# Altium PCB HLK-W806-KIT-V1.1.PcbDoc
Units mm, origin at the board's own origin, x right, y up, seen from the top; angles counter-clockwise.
Board outline 64 x 26 mm, 2 copper layers (Top Layer, Bottom Layer); 46 components, 64 nets, 229 pads, 212 vias.
Unrouted connection lines stored in the file: 24.
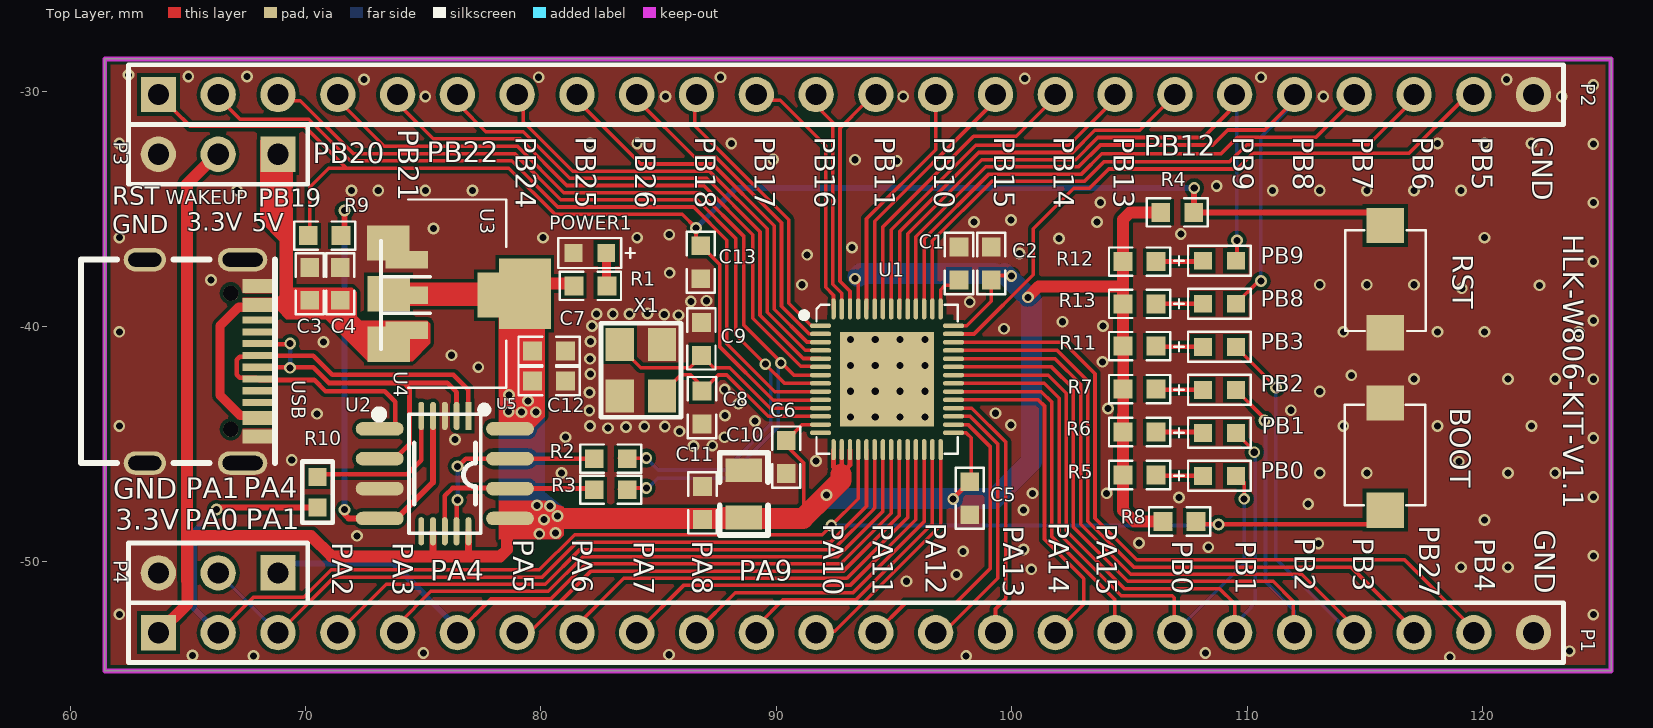
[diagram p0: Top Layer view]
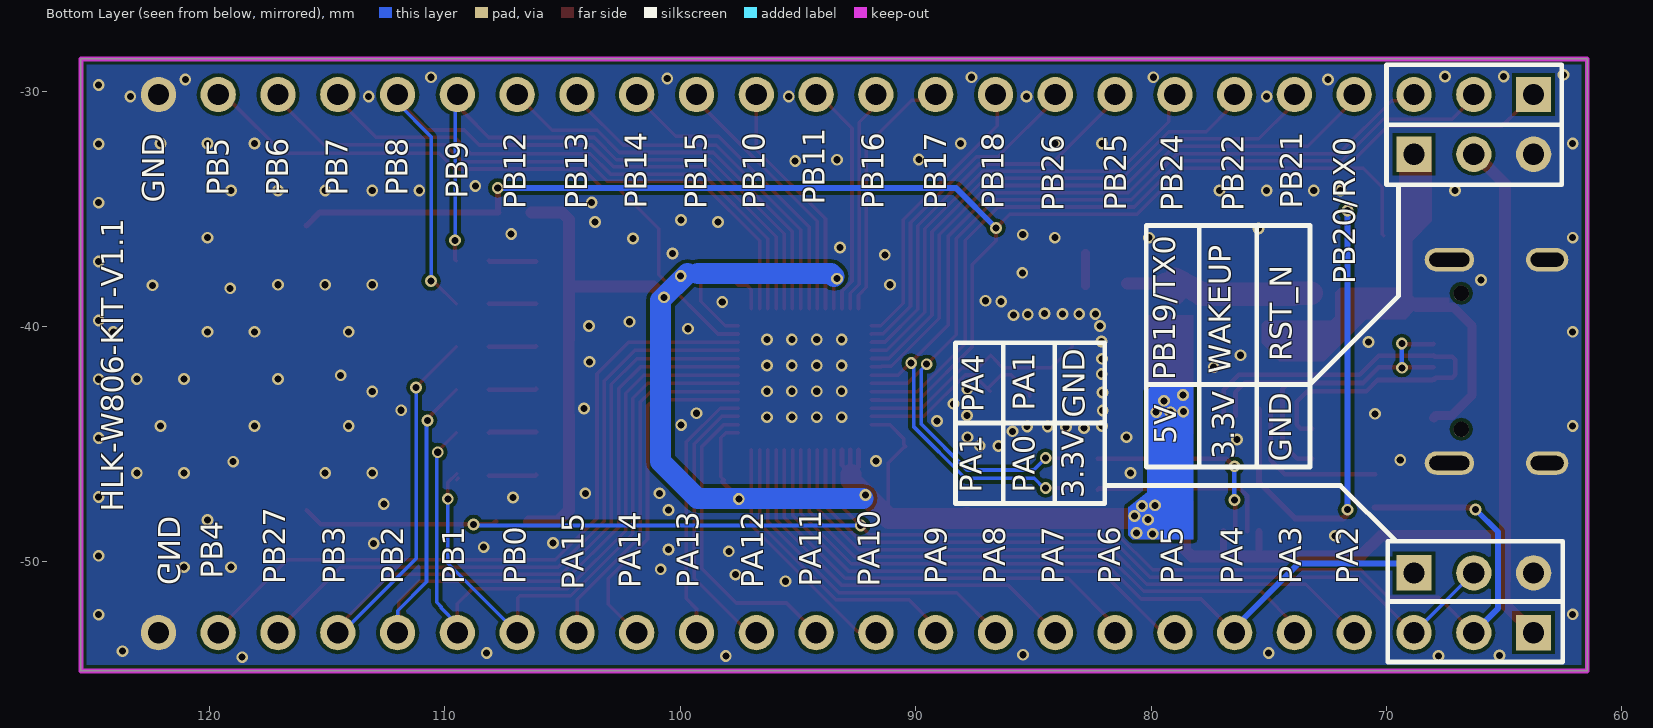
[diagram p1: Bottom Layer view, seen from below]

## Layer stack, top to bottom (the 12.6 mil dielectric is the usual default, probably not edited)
Top Solder: solder mask 0.0102, Solder Resist, Dk 3.5
Top Layer: signal copper 0.0356
Dielectric 1: dielectric 0.32, FR-4, Dk 4.8
Bottom Layer: signal copper 0.0356
Bottom Solder: solder mask 0.0102, Solder Resist, Dk 3.5

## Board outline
61.468,-54.635 125.468,-54.635 125.468,-28.635 61.468,-28.635

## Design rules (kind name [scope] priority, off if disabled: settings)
Clearance [All] p1: gap=0.152 ignorepadtopadclearanceinfootprint=FALSE
PlaneConnect PlaneConnect_1 [InNet('5V')] p1: planeconnectstyle=Direct reliefexpansion=0.508 reliefentries=4 reliefconductorwidth=0.254 reliefairgap=0.254
PlaneConnect [All] p2: planeconnectstyle=Direct reliefexpansion=0.508 reliefentries=4 reliefconductorwidth=0.254 reliefairgap=0.254
PolygonConnect PolygonConnect_1 [InNet('5V')] p1: connectstyle=Direct reliefconductorwidth=0.254 reliefentries=4 polygonreliefangle="90 Angle" airgapwidth=0.254
PolygonConnect [All] p2: connectstyle=Direct reliefconductorwidth=0.254 reliefentries=4 polygonreliefangle="90 Angle" airgapwidth=0.254
RoutingVias [All] p1: holewidth=0.3 width=0.5 viastyle="Through Hole" minholewidth=0.3 minwidth=0.5 maxholewidth=0.5 maxwidth=0.7
SolderMaskExpansion [All] p1: expansion=0.102 istentingtop=FALSE
Width PWER [InNetClass('PWER')] p1: maxlimit=1 minlimit=0.5 preferedwidth=0.75
Width XINHAO [InNetClass('XINHAO')] p2: maxlimit=1 minlimit=0.254 preferedwidth=0.5
Width [All] p3: maxlimit=1 minlimit=0.152 preferedwidth=0.254
29 further rules are at their usual default settings.

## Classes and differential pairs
component class W806-KIT: C1 C2 C3 C4 C5 C6 C7 C8 C9 C10 C11 C12 C13 key1 key2 P1 P2 P3 P4 POWER1 R1 R2 R3 R4 R8 R9 R10 U1 U2 U3 U4 U5 USB X1

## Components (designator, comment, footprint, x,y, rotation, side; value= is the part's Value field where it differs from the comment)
BOOT "按键" 正按小龟 115.875,-47.806 r90 top (schematic designator key1)
C1 "4.7uF" 0603 97.765,-37.327 r90 top
C2 "0.1uF" 0603 99.136,-37.327 r270 top
C3 "10UF" 0603_1 70.18,-38.19 r270 top
C4 "0.1UF" 0603_1 71.476,-38.19 r270 top
C5 "0.1uF" 0603 98.221,-47.301 r90 top
C6 "1uF" 0603 90.424,-45.551 r270 top
C7 "0.1UF" 0603_1 80.351,-41.046 r180 top
C8 "15pF" 0603 86.844,-43.449 r90 top
C9 "15pF" 0603 86.82,-40.528 r90 top
C10 "47uF" R0805 88.621,-47.117 r90 top
C11 "0.1uF" 0603 86.868,-47.498 r90 top
C12 "10UF" 0603_1 80.351,-42.316 r180 top value=100pF
C13 "0.1uF" 0603 86.792,-37.273 r270 top
P1 "Header 24" HDR1X24 63.754,-53.011 r0 top
P2 "Header 24" HDR1X24 63.754,-30.151 r0 top
P3 "Header 3" HDR1X3 68.831,-32.685 r180 top
P4 "Header 3" HDR1X3 68.831,-50.47 r180 top
PB0 "" 0603LED 108.128,-46.346 r0 top
PB1 "" 0603LED 108.128,-44.519 r0 top
PB2 "" 0603LED 108.128,-42.692 r0 top
PB3 "" 0603LED 108.128,-40.865 r0 top
PB8 "" 0603LED 108.128,-39.038 r0 top
PB9 "" 0603LED 108.128,-37.211 r0 top
POWER1 "" 0603LED 82.779,-36.881 r180 top
R1 "4.7K" 0603_1 82.107,-38.278 r0 top
R2 "0" 0603_1 82.971,-45.618 r0 top
R3 "0" 0603_1 82.971,-46.939 r0 top
R4 "10K" 0603_1 107.036,-35.154 r180 top
R5 "4.7K" 0603_1 105.435,-46.312 r0 top
R6 "4.7K" 0603_1 105.435,-44.487 r0 top
R7 "4.7K" 0603_1 105.435,-42.662 r0 top
R8 "10K" 0603_1 107.137,-48.285 r0 top
R9 "1K" 0603_1 70.815,-36.144 r0 top
R10 "1K" "R 0603_L" 70.51,-47.041 r90 top
R11 "4.7K" 0603_1 105.435,-40.836 r0 top
R12 "4.7K" 0603_1 105.435,-37.245 r0 top
R13 "4.7K" 0603_1 105.435,-39.041 r0 top
RST "按键" 正按小龟 115.875,-35.712 r270 top (schematic designator key2)
U1 "W806" "LCC56 - duplicate1" 94.709,-42.245 r0 top
U2 "CH340N" SOP8 75.946,-46.126 r270 top
U3 "AMS1117-3.3" AMS1117 76.149,-38.787 r90 top
U4 "AMS1117-3.3" SOT223 76.53,-38.227 r0 top
U5 "CH340E" MSOP10_L 75.921,-46.253 r180 top
USB "USB_TYPE_C_16Pin" USB-C-16PIN-1 67.266,-37.13 r270 top
X1 "XTAL_40MHz" SMD-3225 84.252,-41.859 r270 top

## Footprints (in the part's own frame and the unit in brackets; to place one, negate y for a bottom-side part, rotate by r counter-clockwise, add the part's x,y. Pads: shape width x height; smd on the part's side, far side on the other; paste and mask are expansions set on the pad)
0603 [mm]
  rect 0.8x0.8 smd: 1(-0.7,0) 2(0.7,0)
  silkscreen extent -1.3,-0.6 1.3,0.6
0603_1 [mm]
  rect 0.8x0.8 smd: 1(-0.7,0) 2(0.7,0)
  silkscreen extent -1.3,-0.6 1.3,0.6
0603LED [mil] "0603贴片LED"
  rect 30x30 smd: 1(0,0) 2(55,0)
  silkscreen extent -48,-25 80,25
AMS1117 [mm]
  rect 1.9x1.8 smd: 0(0.118,-2.059)
  rect 0.75x1.8 smd: 1(1.618,1.841) 2(0.118,1.841) 3(-1.382,1.841)
  silkscreen extent -2.18,0.84 2.42,2.94, body extent -2.13,-2.23 2.37,1.77, height 1.5
HDR1X3 [mm] "Connector; Header; 3 Position"
  rect 1.5x1.5 hole 0.9: 1(0,0)
  round 1.5 hole 0.9: 2(2.54,0) 3(5.08,0)
  silkscreen extent -1.27,-1.27 6.35,1.27
HDR1X24 [mm] "Connector; Header; 24 Position"
  rect 1.5x1.5 hole 0.9: 1(0,0)
  round 1.5 hole 0.9: 2(2.54,0) 3(5.08,0) 4(7.62,0) 5(10.16,0) 6(12.7,0) 7(15.24,0) 8(17.78,0) 9(20.32,0) 10(22.86,0) 11(25.4,0) 12(27.94,0) 13(30.48,0) 14(33.02,0) 15(35.56,0) 16(38.1,0) 17(40.64,0) 18(43.18,0) 19(45.72,0) 20(48.26,0) 21(50.8,0) 22(53.34,0) 23(55.88,0) 24(58.42,0)
  silkscreen extent -1.27,-1.27 59.69,1.27
"LCC56 - duplicate1" [mm]
  oval 0.9x0.19 smd: 1(-2.825,2.275) 2(-2.825,1.925) 3(-2.825,1.575) 4(-2.825,1.225) 5(-2.825,0.875) 6(-2.825,0.525) 7(-2.825,0.175) 8(-2.825,-0.175) 9(-2.825,-0.525) 10(-2.825,-0.875) 11(-2.825,-1.225) 12(-2.825,-1.575) 13(-2.825,-1.925) 14(-2.825,-2.275) 29(2.825,-2.275) 30(2.825,-1.925) 31(2.825,-1.575) 32(2.825,-1.225) 33(2.825,-0.875) 34(2.825,-0.525) 35(2.825,-0.175) 36(2.825,0.175) 37(2.825,0.525) 38(2.825,0.875) 39(2.825,1.225) 40(2.825,1.575) 41(2.825,1.925) 42(2.825,2.275)
  oval 0.19x0.9 smd: 15(-2.275,-2.99) 16(-1.925,-2.99) 17(-1.575,-2.99) 18(-1.225,-2.99) 19(-0.875,-2.99) 20(-0.525,-2.99) 21(-0.175,-2.99) 22(0.175,-2.99) 23(0.525,-2.99) 24(0.875,-2.99) 25(1.225,-2.99) 26(1.575,-2.99) 27(1.925,-2.99) 28(2.275,-2.99) 43(2.275,2.99) 44(1.925,2.99) 45(1.575,2.99) 46(1.225,2.99) 47(0.875,2.99) 48(0.525,2.99) 49(0.175,2.99) 50(-0.175,2.99) 51(-0.525,2.99) 52(-0.875,2.99) 53(-1.225,2.99) 54(-1.575,2.99) 55(-1.925,2.99) 56(-2.275,2.99)
  rect 4x4 smd mask+0.051: 57(0,0)
  silkscreen extent -3,-3.16 3,3.16
MSOP10_L [mm] "塑封体长3mm，宽3mm，脚距0.5"
  rect 0.25x1.2 smd: 1(-1,-2.45)
  oval 0.25x1.2 smd: 2(-0.5,-2.45) 3(0,-2.45) 4(0.5,-2.45) 5(1,-2.45) 6(1,2.45) 7(0.5,2.45) 8(0,2.45) 9(-0.5,2.45) 10(-1,2.45)
  silkscreen extent -1.3,-2.67 2.95,1.3, body extent -1.5,-2.45 1.5,2.45, height 0.95
R0805 [mm]
  rect 1x1.55 smd: 1(-1,0) 2(1,0)
  silkscreen extent -1.75,-1.02 1.75,1.02
"R 0603_L" [mil] "1/10W贴片电阻"
  rect 30x30 smd: 1(-25.59,0) 2(25.59,0)
  silkscreen extent -51,-26 51,26, body extent -31,-16 32,16, height 16
SMD-3225 [mm]
  rect 1.4x1.2 smd: 1(-1.1,-0.9) 2(1.1,-0.9) 3(1.1,0.9) 4(-1.1,0.9)
  silkscreen extent -2,-1.7 2,1.7
SOP8 [mm]
  oval 0.574x2.036 smd: 1(-1.777,-2.792) 2(-0.507,-2.792) 3(0.763,-2.792) 4(2.033,-2.792) 5(2.033,2.743) 6(0.763,2.743) 7(-0.507,2.743) 8(-1.777,2.743)
  silkscreen extent -2.74,-1.55 2.65,1.8
SOT223 [mm]
  rect 2.2x3 smd: 0(2.794,-0.381)
  rect 1.8x1.5 smd: 1(-3.017,1.772) 2(-2.995,-0.384) 3(-2.995,-2.534)
  silkscreen extent -2.16,-4.38 1.99,3.62
USB-C-16PIN-1 [mm]
  oval 1x2.099 hole 0.6 slot 1.7 at 90 deg: 1(0.034,0.061) 2(8.674,0.061)
  oval 1x1.799 hole 0.6 slot 1.4 at 90 deg: 3(0.034,-4.088) 4(8.674,-4.088)
  rect 0.6x1.35 smd: A1B12(1.154,0.736) A4B9(1.954,0.736) B1A12(7.554,0.736) B4A9(6.754,0.736)
  rect 0.3x1.35 smd: A5(3.104,0.736) A6(4.104,0.736) A7(4.604,0.736) A8(2.604,0.736) B5(6.104,0.736) B6(5.104,0.736) B7(3.604,0.736) B8(5.604,0.736)
  round 0.65 hole 0.65 unplated: ""(1.464,-0.438) ""(7.244,-0.438)
  silkscreen extent 0.04,-6.81 8.67,1.45
正按小龟 [mm]
  rect 1.5x1.6 smd: 1(0,0) 2(4.55,0)
  silkscreen extent 0.2,-1.7 4.48,1.73

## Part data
C1 C2 C5 C6 C8 C9 C10 C11 C13: library part "CAP NP_Dup1"
C3 C4 C7: library part CAP, "Capacitor"
C12: library part Cap, "Capacitor"
P1 P2: "Header, 24-Pin"
P3 P4: "Header, 3-Pin"
PB0 PB1 PB2 PB3 PB8 PB9 POWER1: library part LED
R1 R2 R3 R4 R5 R6 R7 R8 R9 R10 R11 R12 R13: library part Res1, "Resistor"
U1 U3 U4: library part Component_1
U2: BOM_JLCPCB Part Class="Extended Part", BOM_Manufacturer="WCH(Jiangsu Qin Heng)"

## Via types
v1: diameter 0.5, hole 0.3, Top Layer to Bottom Layer, tented both sides, 212 vias

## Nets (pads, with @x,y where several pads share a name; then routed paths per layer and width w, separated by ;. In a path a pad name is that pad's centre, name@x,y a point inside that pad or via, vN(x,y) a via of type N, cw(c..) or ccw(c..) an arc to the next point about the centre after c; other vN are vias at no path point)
1: R9.2 U2.4 U5.4 | length 21.6
  Top Layer w0.254: R9.2 71.639,-36.02 71.653,-36.034 v1(71.653,-35.077) ; v1(71.657,-47.787) 71.657,-47.979 71.838,-48.159 U2.4 73.885,-48.159 75.421,-46.623 U5.4 U5.4@75.421,-43.524
  Bottom Layer w0.254: v1(71.657,-47.787) v1@71.657,-35.073
2: R2.1 U2.7 U5.9 | length 8.7
  Top Layer w0.2: U5.9 76.43,-48.694 76.43,-47.395 v1(76.454,-47.371) ; v1(76.463,-45.943) 76.49,-45.943 76.814,-45.619 U2.7 R2.1
  Bottom Layer w0.2: v1(76.454,-47.371) 76.463,-47.362 v1(76.463,-45.943)
3: R3.1 U2.6 U5.8 | length 8
  Top Layer w0.2: U5.8 75.921,-47.194 76.246,-46.869 78.669,-46.869 U2.6 82.22,-46.889 R3.1
5V: C3.2 C4.2 P3.1 U3.3 U4.3 USB.A4B9 USB.B4A9 | length 7
  Top Layer w0.4: USB.B4A9 67.902,-43.784 67.229,-43.784 66.37,-42.925 66.37,-39.975 67.161,-39.184 67.902,-39.184 USB.A4B9
DM1: U2.2 U5.2 USB.A7 USB.B7 | length 16.5
  Top Layer w0.2: USB.A7 70.329,-41.734 70.997,-42.402 74.166,-42.402 ; USB.B7 68.022,-40.753 69.321,-40.753 v1(69.351,-40.723) ; U2.2 73.783,-45.619 74.424,-44.978 74.424,-42.66 74.166,-42.402 ; U5.2 76.421,-42.794 76.029,-42.402 74.166,-42.402
  Bottom Layer w0.2: v1(69.345,-41.759) 69.351,-41.753 v1(69.351,-40.723)
DP1: U2.1 U5.1 USB.A6 USB.B6 | length 21.2
  Top Layer w0.2: USB.B6@67.977,-42.259 67.902,-42.184 67.209,-42.184 67.075,-42.05 67.075,-41.417 67.209,-41.284 67.952,-41.284 USB.A6 68.01,-41.241 70.335,-41.241 71.143,-42.049 76.286,-42.049 76.921,-42.683 U5.1 ; USB.B6 68.042,-42.273 70.371,-42.273 70.851,-42.754 73.368,-42.754 73.812,-43.199 73.812,-44.176 73.64,-44.349 U2.1
GND: BOOT.2 C1.2 C2.1 C3.1 C4.1 C5.1 C6.2 C7.1 C8.1 C9.2 C10.2 C11.2 C12.1 C13.2 P1.24 P2.24 P3.3 P4.3 POWER1.2 RST.2 U1.57 U2.3 U3.1 U4.1 U5.3 USB.1 USB.2 USB.3 USB.4 USB.A1B12 USB.B1A12 X1.2 X1.4
  other v1: 118.618,-54.051 67.793,-54 98.069,-54 65.202,-53.975 85.446,-53.95 75.006,-53.873 108.229,-53.873 123.698,-53.797 124.714,-52.244 62.091,-52.229 95.529,-50.825 97.663,-50.546 100.838,-50.318 119.091,-50.229 121.091,-50.229 124.714,-49.744 97.942,-49.555 100.508,-49.479 108.356,-49.378 113.03,-49.225 105.41,-49.2 72.187,-48.895 120.091,-48.229 100.508,-47.803 112.598,-47.549 107.112,-47.269 124.714,-47.244 100.889,-47.092 104.038,-47.092 80.874,-46.228 113.091,-46.229 115.091,-46.229 121.091,-46.229 123.091,-46.229 118.999,-45.746 91.694,-45.72 69.418,-45.669 86.487,-45.085 87.284,-45.068 76.352,-44.806 124.714,-44.744 81.051,-44.704 87.801,-44.708 85.888,-44.458 82.855,-44.323 83.617,-44.272 84.396,-44.255 85.268,-44.247 62.091,-44.229 82.091,-44.229 114.091,-44.229 118.091,-44.229 122.091,-44.229 99.966,-44.182 89.103,-44.016 93.147,-43.856 94.206,-43.856 95.264,-43.856 96.322,-43.856 87.825,-43.783 70.485,-43.713 99.314,-43.688 82.058,-43.567 111.862,-43.561 104.089,-43.485 88.392,-43.287 82.069,-42.806 113.091,-42.763 93.147,-42.755 94.206,-42.755 95.264,-42.755 96.322,-42.755 87.808,-42.672 117.091,-42.229 121.091,-42.229 123.091,-42.229 124.714,-42.244 114.431,-42.077 82.1,-42.024 77.343,-41.732 93.147,-41.655 94.206,-41.655 95.264,-41.655 96.322,-41.655 103.861,-41.504 82.09,-41.378 76.2,-41.224 70.764,-40.665 82.111,-40.638 93.147,-40.554 94.206,-40.554 95.264,-40.554 96.322,-40.554 62.091,-40.229 114.091,-40.229 118.091,-40.229 120.091,-40.229 124.091,-40.229 99.674,-40.098 82.169,-39.98 103.886,-39.981 102.159,-39.802 124.714,-39.744 85.852,-39.522 85.242,-39.497 82.372,-39.472 83.058,-39.472 83.769,-39.472 84.531,-39.446 98.222,-38.964 86.373,-38.945 87.032,-38.91 119.126,-38.38 122.428,-38.253 91.091,-38.229 113.091,-38.229 115.091,-38.229 117.091,-38.229 65.989,-38.024 85.472,-37.721 124.714,-37.244 91.313,-36.957 100.33,-36.906 93.218,-36.652 102.011,-36.261 62.091,-36.229 80.091,-36.229 84.091,-36.229 120.091,-36.229 85.456,-36.102 107.188,-36.068 75.438,-35.84 98.406,-35.564 103.632,-35.56 99.979,-35.474 103.77,-34.737 124.714,-34.744 67.091,-34.229 71.954,-34.229 73.091,-34.229 75.091,-34.229 77.091,-34.229 111.091,-34.229 113.091,-34.229 115.091,-34.229 117.091,-34.229 119.091,-34.229 108.712,-34.036 95.123,-32.969 89.872,-32.909 93.345,-32.918 62.091,-32.229 82.091,-32.229 84.091,-32.229 88.091,-32.229 118.091,-32.229 120.091,-32.229 122.091,-32.229 124.714,-32.244 75.091,-30.229 85.294,-30.229 95.396,-30.229 113.243,-30.229 123.37,-30.229 124.714,-29.744 124.714,-29.744 72.492,-29.515 121.031,-29.515 100.559,-29.464 79.908,-29.413 87.63,-29.413 110.592,-29.413 65.024,-29.388 67.513,-29.388 62.484,-29.312
NetC1_1: C1.1 U1.43 | length 1.8
  Top Layer w0.152: U1.43 96.984,-38.437 97.168,-38.252 97.539,-38.252 C1.1
NetPB0_1: PB0.1 R5.2 | length 2
  Top Layer w0.2: R5.2 106.17,-46.346 PB0.1
NetPB1_1: PB1.1 R6.2 | length 2
  Top Layer w0.2: R6.2 108.095,-44.487 PB1.1
NetPB2_1: PB2.1 R7.2 | length 2
  Top Layer w0.2: R7.2 106.166,-42.692 PB2.1
NetPB3_1: PB3.1 R11.2 | length 2
  Top Layer w0.2: R11.2 106.164,-40.865 PB3.1
NetPB8_1: PB8.1 R13.2 | length 2
  Top Layer w0.2: R13.2 106.138,-39.038 PB8.1
NetPB9_1: PB9.1 R12.2 | length 2
  Top Layer w0.2: R12.2 108.094,-37.245 PB9.1
NetPOWER1_1: POWER1.1 R1.2 | length 1.4
  Top Layer w0.381: R1.2@82.793,-38.264 POWER1.1@82.793,-36.895
NetR10_2: R10.2 U5.5 | length 6.8
  Top Layer w0.2: R10.2@70.485,-46.277 74.32,-46.277 74.921,-45.676 U5.5 U5.5@74.921,-43.524
PA0/BOOT: BOOT.1 P1.2 R8.2 R10.1 U1.18 | length 66.8
  Top Layer w0.152: P1.2 67.794,-51.511 69.927,-51.511 71.095,-50.343 79.937,-50.343 81.434,-48.846 91.952,-48.846 v1(92.342,-48.456) 93.478,-47.319 93.478,-45.24 U1.18
  Top Layer w0.2: R8.2 107.962,-48.41 v1(108.795,-48.41) 115.271,-48.41 BOOT.1
  Top Layer w0.254: v1(66.218,-47.777) 66.284,-47.777 66.371,-47.691 R10.1
  Bottom Layer w0.152: v1(92.342,-48.456) 108.749,-48.456 v1(108.795,-48.41)
  Bottom Layer w0.254: v1(66.218,-47.777) 65.262,-48.734 65.262,-51.978 P1.2
PA1: P1.3 P4.2 U1.19 | length 33.2
  Top Layer w0.152: P1.3 68.858,-53.011 71.222,-50.648 80.063,-50.648 81.536,-49.174 92.303,-49.174 93.834,-47.643 U1.19
  Bottom Layer w0.152: P4.2 P1.3
PA2: P1.4 U1.20 | length 27.5
  Top Layer w0.152: P1.4 73.432,-50.952 80.189,-50.952 81.662,-49.479 92.429,-49.479 94.138,-47.77 94.138,-47.748 94.184,-47.703 U1.20
PA3: P1.5 U1.21 | length 25.6
  Top Layer w0.152: P1.5 73.914,-52.671 75.328,-51.257 80.316,-51.257 81.789,-49.784 92.606,-49.784 94.534,-47.857 U1.21
PA4: P1.6 P4.1 U1.22 | length 32.2
  Top Layer w0.152: P1.6 77.883,-51.581 80.422,-51.581 81.915,-50.089 92.735,-50.089 94.884,-47.94 U1.22
  Bottom Layer w0.254: P4.1@68.831,-50.063 73.729,-50.063 76.454,-52.788 P1.6
PA5: P1.7 U1.23 | length 21.1
  Top Layer w0.152: P1.7 79.008,-52.997 79.524,-52.997 82.127,-50.394 92.861,-50.394 95.234,-48.021 U1.23
PA6: P1.8 U1.24 | length 19.1
  Top Layer w0.152: P1.8 81.534,-52.692 83.528,-50.698 93.003,-50.698 95.584,-48.118 U1.24
PA7: P1.9 U1.25 | length 16.8
  Top Layer w0.152: P1.9 84.074,-52.987 86.058,-51.003 93.137,-51.003 95.934,-48.207 U1.25
PA8: P1.10 U1.26 | length 14.7
  Top Layer w0.152: P1.10 86.614,-52.959 88.265,-51.308 93.263,-51.308 96.284,-48.288 U1.26
PA9: P1.11 U1.27 | length 12.4
  Top Layer w0.152: P1.11@89.154,-52.604 89.294,-52.604 90.286,-51.613 93.391,-51.613 96.626,-48.378 96.626,-45.243 U1.27
PA10: P1.12 U1.28 | length 10.4
  Top Layer w0.152: P1.12 91.753,-52.951 92.484,-52.951 96.984,-48.451 U1.28
PA11: P1.13 U1.30 | length 13.1
  Top Layer w0.152: P1.13 95.493,-51.752 97.627,-51.752 99.101,-50.278 99.101,-45.121 98.15,-44.17 U1.30
PA12: P1.14 U1.31 | length 11.7
  Top Layer w0.152: P1.14 97.098,-53.011 99.405,-50.704 99.405,-44.994 98.231,-43.82 U1.31
PA13: P1.15 U1.32 | length 11.1
  Top Layer w0.152: U1.32 98.312,-43.47 99.754,-44.912 99.754,-51.562 99.314,-52.002 P1.15
PA14: P1.16 U1.33 | length 14.8
  Top Layer w0.152: U1.33 97.539,-43.115 97.693,-43.115 97.699,-43.11 101.124,-43.11 101.397,-43.382 101.397,-49.047 103.061,-50.711 103.061,-51.804 P1.16
PA15: P1.17 U1.34 | length 15.3
  Top Layer w0.152: U1.34 101.264,-42.77 101.702,-43.208 101.702,-48.756 101.713,-48.767 101.713,-48.932 104.379,-51.598 104.379,-52.996 P1.17
PB0: P1.18 PB0.2 U1.35 | length 26
  Top Layer w0.152: U1.35 101.384,-42.42 102.017,-43.053 102.017,-48.806 104.654,-51.442 106.825,-51.442 106.914,-51.531 106.914,-52.991 P1.18 ; PB0.2@109.449,-46.457 PB0.2@109.499,-46.507 ; PB0.2@109.499,-46.253 109.878,-46.632 v1(109.878,-47.325)
  Bottom Layer w0.152: P1.18@106.934,-52.604 107.329,-52.604 109.878,-50.055 v1(109.878,-47.325)
PB1: P1.19 PB1.2 U1.36 | length 29
  Top Layer w0.152: U1.36@97.539,-42.075 101.555,-42.075 102.322,-42.843 102.322,-48.679 104.78,-51.137 108.824,-51.137 109.474,-51.787 P1.19@109.474,-52.604 ; PB1.2 110.308,-45.303 v1(110.308,-45.345)
  Bottom Layer w0.152: P1.19@109.516,-52.604 110.151,-51.969 110.151,-51.928 110.357,-51.721 110.357,-45.394 v1(110.308,-45.345)
PB2: P1.20 PB2.2 U1.37 | length 34.3
  Top Layer w0.152: U1.37 101.697,-41.72 102.627,-42.65 102.627,-48.525 104.934,-50.832 111.11,-50.832 111.973,-51.695 111.973,-52.563 P1.20@112.014,-52.604 ; PB2.2 110.744,-43.911 v1(110.744,-43.993)
  Bottom Layer w0.152: v1(110.744,-43.993) 110.787,-44.036 110.787,-50.849 112.014,-52.076 P1.20
PB3: P1.21 PB3.2 U1.38 | length 39.7
  Top Layer w0.152: U1.38 101.844,-41.37 102.932,-42.458 102.932,-48.399 105.06,-50.527 112.322,-50.527 114.554,-52.76 P1.21 ; PB3.2 111.227,-42.567 v1(111.227,-42.596)
  Bottom Layer w0.152: v1(111.227,-42.596) 111.227,-49.862 114.024,-52.66 114.498,-52.66 P1.21@114.554,-52.604
PB4: P1.23 U1.40 | length 30.9
  Top Layer w0.152: U1.40 102.202,-40.67 103.541,-42.009 103.541,-48.147 105.313,-49.918 116.692,-49.918 119.634,-52.86 P1.23
PB5: P2.23 U1.41 | length 27.1
  Top Layer w0.152: U1.41 98.404,-40.32 100.919,-37.805 100.919,-35.854 102.637,-34.136 103.307,-34.136 104.132,-33.311 109.386,-33.311 109.388,-33.31 109.591,-33.31 110.266,-32.635 116.898,-32.635 119.068,-30.465 119.212,-30.465 P2.23@119.38,-30.633
PB6_TX1: P2.22 U1.44 | length 26
  Top Layer w0.152: U1.44 96.634,-36.362 99.164,-33.831 103.098,-33.831 103.922,-33.006 109.26,-33.006 109.987,-32.28 115.157,-32.28 117.094,-30.343 P2.22
PB7_RX1: P2.21 U1.45 | length 23.6
  Top Layer w0.152: U1.45 96.284,-36.281 99.038,-33.526 102.971,-33.526 103.833,-32.664 108.895,-32.664 109.599,-31.96 112.931,-31.96 114.258,-30.633 P2.21@114.554,-30.633
PB8: P2.20 PB8.2 U1.46 | length 31.8
  Top Layer w0.152: U1.46 95.934,-36.191 98.903,-33.222 102.845,-33.222 103.774,-32.292 108.54,-32.292 109.177,-31.655 110.76,-31.655 112.014,-30.401 P2.20 ; PB8.2 110.422,-38.141 110.525,-38.141 v1(110.592,-38.075)
  Bottom Layer w0.152: v1(110.592,-38.075) 110.592,-31.936 112.014,-30.514 P2.20
PB9: P2.19 PB9.2 U1.47 | length 26
  Top Layer w0.152: U1.47 95.584,-36.069 98.736,-32.917 102.719,-32.917 103.663,-31.972 108.135,-31.972 109.216,-30.891 109.216,-30.773 109.356,-30.633 P2.19@109.474,-30.633 ; PB9.2 109.576,-37.16 v1(109.576,-36.343)
  Bottom Layer w0.152: P2.19@109.474,-30.633 109.572,-30.731 109.572,-36.339 v1(109.576,-36.343)
PB10: P2.14 U1.52 | length 9.8
  Top Layer w0.152: U1.52 93.835,-39.254 93.835,-35.428 96.774,-32.488 P2.14@96.774,-30.633
PB11: P2.13 U1.54 | length 9.8
  Top Layer w0.152: U1.54 93.134,-38.511 92.71,-38.087 92.71,-31.574 93.743,-30.541 94.141,-30.541 P2.13@94.234,-30.633
PB12: P2.18 U1.48 | length 17.2
  Top Layer w0.152: U1.48@95.239,-39.25 95.239,-35.972 98.599,-32.612 102.593,-32.612 103.537,-31.668 105.445,-31.668 106.508,-30.605 106.905,-30.605 P2.18@106.934,-30.633
PB13: P2.17 U1.49 | length 15
  Top Layer w0.152: U1.49@94.889,-39.25 94.889,-35.895 94.934,-35.849 94.934,-35.846 98.473,-32.307 102.428,-32.307 104.102,-30.633 P2.17@104.394,-30.633
PB14: P2.16 U1.50 | length 13.2
  Top Layer w0.152: U1.50 94.534,-35.771 98.384,-31.92 100.199,-31.92 101.854,-30.265 P2.16
PB15: P2.15 U1.51 | length 10.9
  Top Layer w0.152: U1.51 94.184,-35.53 99.08,-30.633 P2.15@99.314,-30.633
PB16: P2.12 U1.55 | length 9.1
  Top Layer w0.152: P2.12@91.707,-30.633 91.812,-30.633 91.952,-30.773 91.952,-30.879 92.405,-31.332 92.405,-38.214 92.784,-38.592 U1.55
PB17: P2.11 U1.56 | length 10.9
  Top Layer w0.152: P2.11 89.397,-30.394 90.173,-30.394 92.1,-32.322 92.1,-38.34 92.434,-38.673 U1.56
PB18: P2.10 U1.1 | length 12.3
  Top Layer w0.152: P2.10 86.532,-30.233 86.532,-31.473 87.547,-32.489 90.528,-35.47 90.528,-39.018 91.462,-39.951 91.475,-39.951 91.494,-39.97 U1.1
PB19_TX0: P2.3 R2.2 U1.8 | length 40.5
  Top Layer w0.152: P2.3@68.805,-30.409 69.784,-30.409 72.031,-32.656 78.884,-32.656 80.85,-34.623 86.643,-34.623 88.283,-36.263 88.283,-40.355 v1(89.535,-41.605) 90.348,-42.42 U1.8 ; R2.2@83.34,-45.593 v1(84.48,-45.593)
  Bottom Layer w0.152: v1(84.48,-45.593) 84.988,-46.101 87.819,-46.101 89.773,-44.148 89.773,-41.835 89.586,-41.648 89.543,-41.605 v1(89.535,-41.605)
PB20_RX0: P2.4 R3.2 U1.7 | length 38.4
  Top Layer w0.152: P2.4 71.374,-30.374 73.352,-32.351 79.01,-32.351 80.977,-34.318 86.769,-34.318 88.628,-36.177 88.628,-39.947 90.215,-41.535 90.751,-42.07 U1.7 ; R3.2@83.34,-46.914 83.391,-46.863 v1(84.48,-46.863)
  Bottom Layer w0.152: v1(84.48,-46.863) 84.557,-46.863 84.969,-46.45 ; 84.963,-46.45 84.969,-46.45 ; v1(90.195,-41.554) 90.195,-41.648 90.077,-41.766 90.077,-44.274 87.901,-46.45 84.969,-46.45 ; v1@90.246,-41.554 v1@90.246,-41.529
PB21: P2.5 U1.6 | length 24.5
  Top Layer w0.152: P2.5@74.032,-30.633 75.428,-32.03 79.119,-32.03 81.103,-34.013 86.916,-34.013 89.004,-36.101 89.004,-39.652 91.045,-41.694 91.467,-41.694 91.494,-41.72 U1.6
PB22: P2.6 U1.5 | length 21.8
  Top Layer w0.152: P2.6@76.572,-30.633 77.663,-31.725 79.246,-31.725 81.229,-33.708 87.042,-33.708 89.309,-35.975 89.309,-39.526 91.146,-41.363 91.876,-41.363 U1.5
PB24: P2.7 U1.4 | length 19.5
  Top Layer w0.152: P2.7@79.112,-30.633 79.252,-30.773 79.252,-31.3 81.355,-33.404 87.169,-33.404 89.614,-35.849 89.614,-39.4 91.227,-41.013 91.876,-41.013 U1.4
PB25: P2.8 U1.3 | length 16.9
  Top Layer w0.152: P2.8 81.534,-30.392 84.241,-33.099 87.295,-33.099 89.919,-35.722 89.919,-39.274 91.308,-40.663 91.876,-40.663 U1.3
PB26: P2.9 U1.2 | length 14.2
  Top Layer w0.152: P2.9 84.074,-30.358 86.51,-32.794 87.421,-32.794 90.223,-35.596 90.223,-39.147 91.389,-40.313 91.876,-40.313 U1.2
PB27: P1.22 U1.39 | length 28.1
  Top Layer w0.152: U1.39 101.937,-41.02 103.237,-42.319 103.237,-48.273 105.186,-50.223 114.416,-50.223 117.094,-52.9 P1.22
RESET: C13.1 P2.1 R4.1 R9.1 RST.1 U1.10 | length 71.2
  Top Layer w0.152: P2.1 64.428,-30.825 65.092,-31.489 67.079,-31.489 67.094,-31.504 69.975,-31.504 71.745,-33.274 ; R9.1 70.18,-36.079 70.18,-34.087 70.993,-33.274 71.745,-33.274 ; U1.10 91.876,-43.127 91.545,-43.127 91.54,-43.132 89.871,-43.132 87.592,-40.854 87.592,-37.363 86.592,-36.363 v1(86.592,-35.818) 86.007,-35.232 80.598,-35.232 78.64,-33.274 71.745,-33.274
  Top Layer w0.254: v1(107.758,-34.115) 107.758,-35.131 R4.1 115.316,-35.154 RST.1
  Bottom Layer w0.254: v1(86.592,-35.818) 88.295,-34.115 v1(107.758,-34.115)
VCC3_3: C2.2 C5.2 C6.1 C7.2 C10.1 C11.1 C12.2 P1.1 P3.2 R1.1 R4.2 R5.1 R6.1 R7.1 R8.1 R11.1 R12.1 R13.1 U1.13 U1.15 U1.16 U1.17 U1.29 U1.42 U1.53 U2.5 U2.8 U3.0 U3.2 U4.0 U4.2 U5.7 U5.10 | length 124.1
  Top Layer w0.152: 91.161,-48.129 91.161,-45.787 90.474,-45.101 90.424,-45.101 90.518,-45.007 90.518,-44.761 91.109,-44.17 U1.13 ; 92.713,-46.101 92.784,-46.03 ; U1.17@93.128,-45.24 U1.17 ; v1(93.35,-37.972) 93.484,-38.106 U1.53 ; U1.42 98.098,-39.97 99.136,-38.932 C2.2 99.328,-37.835 99.965,-37.835 v1(99.989,-37.859) ; U1.29@97.539,-44.525 98.074,-44.525 98.28,-44.731 98.28,-46.393 C5.2@98.147,-46.526
  Top Layer w0.2: v1(97.519,-47.331) 97.519,-47.303 C5.2
  Top Layer w0.203: U1.15 92.434,-45.822 92.434,-45.967 92.748,-46.281 93.128,-45.901 U1.17@93.128,-45.24 ; 92.784,-46.03 U1.16
  Top Layer w0.3: U5.7 75.421,-49.686 75.455,-49.721 ; 76.921,-49.721 U5.10
  Top Layer w0.5: P1.1 64.989,-51.775 64.989,-48.894 ; 64.971,-50.8 64.971,-33.941 66.227,-32.685 P3.2 ; 65.123,-48.894 70.23,-48.894 71.108,-49.772 78.278,-49.772 78.562,-49.487 78.562,-48.743 78.613,-48.692 ; U4.0@79.757,-38.175 R1.1@81.026,-38.175 ; v1(100.696,-38.762) 101.155,-38.303 104.735,-38.303 ; R5.1@104.735,-46.363 104.735,-47.815 105.206,-48.285 R8.1 ; R5.1 R6.1 104.735,-43.761 104.742,-43.755 104.742,-40.548 104.735,-40.542 104.735,-35.454 105.028,-35.161 R4.2@106.322,-35.161
  Top Layer w0.889: U2.5 87.782,-48.159 ; 87.833,-48.117 87.875,-48.158 91.131,-48.158 ; 91.161,-48.129 v1(92.131,-47.158) 92.748,-46.541 92.748,-46.281
  Top Layer w1: U4.2@73.205,-38.585 73.206,-38.584 U4.2@73.978,-38.584 ; U4.2@73.978,-38.636 U3.0@77.878,-38.636 ; U3.0@77.856,-38.602 78.102,-38.47 78.726,-38.135 U4.0@78.994,-37.992 ; U4.0@78.994,-38.583 U4.0@79.376,-38.201
  Bottom Layer w0.889: v1@92.239,-47.308 99.277,-47.308 100.838,-45.746 100.838,-38.888 99.695,-37.745 ; v1@93.472,-37.872 93.599,-37.745 99.259,-37.745
  other v1: 79.936,-48.811 80.621,-48.779 80.137,-48.209 80.704,-48.049 80.384,-47.633 79.832,-47.6 79.178,-43.643 79.787,-43.643 78.632,-43.62 79.457,-43.161 78.644,-42.918
WAKEUP: P2.2 U1.9 | length 33.5
  Top Layer w0.152: P2.2 66.294,-30.273 67.22,-31.199 70.143,-31.199 71.905,-32.961 78.758,-32.961 80.366,-34.569 80.724,-34.928 86.49,-34.928 87.903,-36.341 87.903,-40.733 89.939,-42.77 U1.9
XIN: C8.2 U1.12 X1.3 | length 8.4
  Top Layer w0.152: X1.3 85.152,-42.859 85.955,-42.056 85.987,-42.056 86.36,-42.056 C8.2@86.875,-42.57 ; C8.2 87.531,-42.062 87.903,-42.062 89.661,-43.82 U1.12
XOUT: C9.1 U1.11 X1.1 | length 10.2
  Top Layer w0.152: X1.1 83.352,-40.859 84.244,-41.751 86.327,-41.751 86.496,-41.581 86.496,-41.552 C9.1 87.35,-41.757 88.029,-41.757 89.742,-43.47 U1.11
pads on no net: U1.14 U5.6 USB. USB.A5 USB.A8 USB.B5 USB.B8

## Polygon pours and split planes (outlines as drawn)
GND on Top Layer "GND_L01_P017" (solid, pour order 17): 61.62,-28.828 125.509,-28.828 125.509,-54.507 61.62,-54.507
no net on Top Layer "NONET_L02_P-001" (solid, pour order 18): 67.564,-38.811
no net on Top Layer "NONET_L01_P014" (solid, pour order 14): 66.584,-40.793
GND on Bottom Layer "GND_L02_P015" (solid, pour order 15): 61.595,-28.829 125.484,-28.829 125.484,-54.508 61.595,-54.508

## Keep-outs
Keep-Out Layer:
  the board outline again, w0.2

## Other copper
Top Layer:
  region net 5V: 69.469,-38.405 69.469,-32.283 69.266,-32.08 68.072,-32.08 68.072,-35.535 68.91,-36.373 68.91,-38.811 69.173,-38.811
  region net VCC3_3: 78.221,-47.396 80.213,-47.396 80.975,-47.65 80.975,-48.87 80.797,-49.047 78.221,-49.047
  region net 5V: 67.335,-38.786 68.809,-38.786 69.24,-38.354 71.984,-38.354 72.187,-38.557 72.187,-39.573 72.365,-39.751 75.184,-39.751 75.311,-39.878 75.311,-40.716 74.549,-41.478 72.644,-41.478 70.866,-39.7 69.19,-39.7 68.834,-39.345 68.809,-39.37 67.335,-39.37
  region net VCC3_3: 78.207,-39.522 78.207,-44.577 79.426,-44.577 80.162,-43.84 80.162,-39.522
  pour cut-out: 78.359,-40.03
  pour cut-out: 92.205,-39.485 97.497,-39.485 97.536,-39.523 97.536,-44.795 97.096,-45.235 92.175,-45.235 92.175,-39.515
Bottom Layer:
  region net VCC3_3: 78.209,-42.57 78.209,-49.047 80.797,-49.047 80.975,-48.869 80.975,-47.681 80.162,-47.054 80.162,-42.723 80.01,-42.57
  region net GND: 78.207,-43.536

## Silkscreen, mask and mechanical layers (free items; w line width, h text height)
Top Overlay:
  circle w0.254: c91.186,-39.523 r0.127
  text "PB21" at 73.635,-31.623 h1.5 r270
  text "PB24" at 78.638,-31.947 h1.5 r270
  text "PB25" at 81.178,-31.947 h1.5 r270
  text "PB26" at 83.718,-31.947 h1.5 r270
  text "PB18" at 86.258,-31.947 h1.5 r270
  text "PB17" at 88.798,-31.947 h1.5 r270
  text "PB16" at 91.338,-31.947 h1.5 r270
  text "PB11" at 93.878,-31.947 h1.5 r270
  text "PB10" at 96.418,-31.947 h1.5 r270
  text "PB15" at 98.958,-31.947 h1.5 r270
  text "PB14" at 101.498,-31.947 h1.5 r270
  text "PB13" at 104.038,-31.947 h1.5 r270
  text "PB9" at 109.118,-31.947 h1.5 r270
  text "PB8" at 111.658,-31.947 h1.5 r270
  text "PB7" at 114.198,-31.947 h1.5 r270
  text "PB6" at 116.738,-31.947 h1.5 r270
  text "PB5" at 119.278,-31.947 h1.5 r270
  text "GND" at 121.818,-31.947 h1.5 r270
  text "PB12" at 105.613,-33.045 h1.5
  text "PB22" at 75.159,-33.325 h1.5
  text "PB20" at 70.307,-33.376 h1.5
  text "WAKEUP" at 64.059,-35.001 h1
  text "RST" at 61.798,-35.077 h1.3
  text "PB19" at 67.996,-35.179 h1.3
  text "HLK-W806-KIT-V1.1" at 123.139,-36.093 h1.5 r270
  text "3.3V" at 64.948,-36.195 h1.3
  text "5V" at 67.716,-36.22 h1.3
  text "GND" at 61.798,-36.297 h1.3
  text "PA4" at 67.386,-47.574 h1.5
  text "PA1" at 64.922,-47.6 h1.5
  text "GND" at 61.824,-47.625 h1.5
  text "PA14" at 101.27,-48.311 h1.5 r270
  text "PA12" at 96.063,-48.336 h1.5 r270
  text "PA10" at 91.694,-48.387 h1.5 r270
  text "PA11" at 93.802,-48.387 h1.5 r270
  text "PA15" at 103.327,-48.387 h1.5 r270
  text "PA13" at 99.339,-48.463 h1.5 r270
  text "PB27" at 117.018,-48.463 h1.5 r270
  text "GND" at 121.92,-48.641 h1.5 r270
  text "PA1" at 67.462,-48.92 h1.5
  text "3.3V" at 61.925,-48.946 h1.5
  text "PA0" at 64.872,-48.946 h1.5
  text "PB2" at 111.735,-48.971 h1.5 r270
  text "PB3" at 114.224,-48.971 h1.5 r270
  text "PB4" at 119.38,-48.997 h1.5 r270
  text "PA5" at 78.537,-49.047 h1.5 r270
  text "PA6" at 81.026,-49.047 h1.5 r270
  text "PA8" at 86.131,-49.098 h1.5 r270
  text "PB0" at 106.528,-49.098 h1.5 r270
  text "PB1" at 109.22,-49.098 h1.5 r270
  text "PA7" at 83.642,-49.124 h1.5 r270
  text "PA2" at 70.841,-49.174 h1.5 r270
  text "PA3" at 73.406,-49.174 h1.5 r270
  text "PA4" at 75.311,-51.105 h1.5
  text "PA9" at 88.417,-51.105 h1.5
Bottom Overlay:
  lines w0.2: 62.509,-51.689 69.952,-51.689 ; 62.56,-31.432 70.002,-31.432 ; 69.494,-34.036 69.494,-38.71 73.254,-42.469 80.213,-42.469 ; 69.634,-49.086 71.958,-46.761 81.915,-46.761 ; 75.514,-45.872 75.514,-35.789 ; 77.953,-45.872 77.953,-35.712 ; 80.137,-35.712 73.254,-35.712 73.254,-45.974 80.213,-45.974 80.213,-35.712 ; 81.966,-44.107 88.316,-44.107 ; 84.099,-47.447 84.099,-40.716 ; 86.284,-47.523 86.284,-40.716 ; 62.509,-54.254 69.952,-54.254 69.952,-49.124 62.509,-49.124 62.509,-54.254 ; 62.56,-33.985 62.56,-28.88 70.002,-28.88 70.002,-33.985 62.56,-33.985 ; 81.966,-47.523 88.316,-47.523 88.316,-40.691 81.966,-40.691 81.966,-47.523
  text "PB8" at 111.274,-34.451 h1.6 r270
  text "PB7" at 113.809,-34.451 h1.6 r270
  text "PB6" at 116.343,-34.451 h1.6 r270
  text "PB5" at 118.878,-34.451 h1.6 r270
  text "PB9" at 108.712,-34.57 h1.6 r270
  text "GND" at 121.615,-34.747 h1.6 r270
  text "PB11" at 93.548,-34.823 h1.6 r270
  text "PB21" at 73.254,-35.001 h1.6 r270
  text "PB14" at 101.117,-35.001 h1.6 r270
  text "PB18" at 85.954,-35.027 h1.6 r270
  text "PB17" at 88.392,-35.027 h1.6 r270
  text "PB16" at 91.034,-35.027 h1.6 r270
  text "PB10" at 96.088,-35.027 h1.6 r270
  text "PB15" at 98.552,-35.027 h1.6 r270
  text "PB13" at 103.632,-35.027 h1.6 r270
  text "PB12" at 106.248,-35.027 h1.6 r270
  text "PB25" at 80.747,-35.077 h1.6 r270
  text "PB22" at 75.743,-35.103 h1.6 r270
  text "PB24" at 78.334,-35.103 h1.6 r270
  text "PB26" at 83.388,-35.103 h1.6 r270
  text "PB20/RX0" at 71.018,-38.202 h1.6 r270
  text "RST_N" at 73.711,-41.478 h1.6 r270
  text "WAKEUP" at 76.302,-42.012 h1.6 r270
  text "PB19/TX0" at 78.664,-42.291 h1.6 r270
  text "PA1" at 84.623,-43.58 h1.6 r270
  text "PA4" at 86.794,-43.653 h1.6 r270
  text "GND" at 82.501,-43.873 h1.6 r270
  text "5V" at 78.613,-45.009 h1.6 r270
  text "3.3V" at 76.149,-45.644 h1.6 r270
  text "GND" at 73.736,-45.745 h1.6 r270
  text "PA0" at 84.623,-47.068 h1.6 r270
  text "PA1" at 86.868,-47.066 h1.6 r270
  text "3.3V" at 82.55,-47.295 h1.6 r270
  text "HLK-W806-KIT-V1.1" at 123.342,-47.879 h1.6 r270
  text "PB4" at 119.126,-50.724 h1.6 r270
  text "PA2" at 70.891,-50.952 h1.6 r270
  text "PA3" at 73.304,-50.952 h1.6 r270
  text "PA4" at 75.794,-50.952 h1.6 r270
  text "PA5" at 78.349,-50.952 h1.6 r270
  text "PA6" at 81.001,-50.952 h1.6 r270
  text "PA7" at 83.388,-50.952 h1.6 r270
  text "PA8" at 85.877,-50.952 h1.6 r270
  text "PA9" at 88.374,-50.952 h1.6 r270
  text "PB0" at 106.248,-50.952 h1.6 r270
  text "PB1" at 108.864,-50.952 h1.6 r270
  text "PB2" at 111.455,-50.952 h1.6 r270
  text "PB3" at 113.944,-50.952 h1.6 r270
  text "PB27" at 116.459,-50.952 h1.6 r270
  text "GND" at 122.504,-51.003 h1.6 r90
  text "PA10" at 91.211,-51.054 h1.6 r270
  text "PA11" at 93.701,-51.054 h1.6 r270
  text "PA12" at 96.164,-51.13 h1.6 r270
  text "PA13" at 98.908,-51.13 h1.6 r270
  text "PA14" at 101.371,-51.13 h1.6 r270
  text "PA15" at 103.784,-51.181 h1.6 r270

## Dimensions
61.468,-28.635 to 61.468,-54.635 on Top Overlay
61.468,-28.635 to 125.468,-28.635 on Top Overlay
